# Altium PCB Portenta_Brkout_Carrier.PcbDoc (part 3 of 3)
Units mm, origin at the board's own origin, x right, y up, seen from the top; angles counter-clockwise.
Board outline 163.96 x 72.14 mm, 4 copper layers (Top, GND, PWR, Bottom), stack 1.612 mm thick; 71 components, 171 nets, 700 pads, 387 vias.
Unrouted connection lines stored in the file: 2.
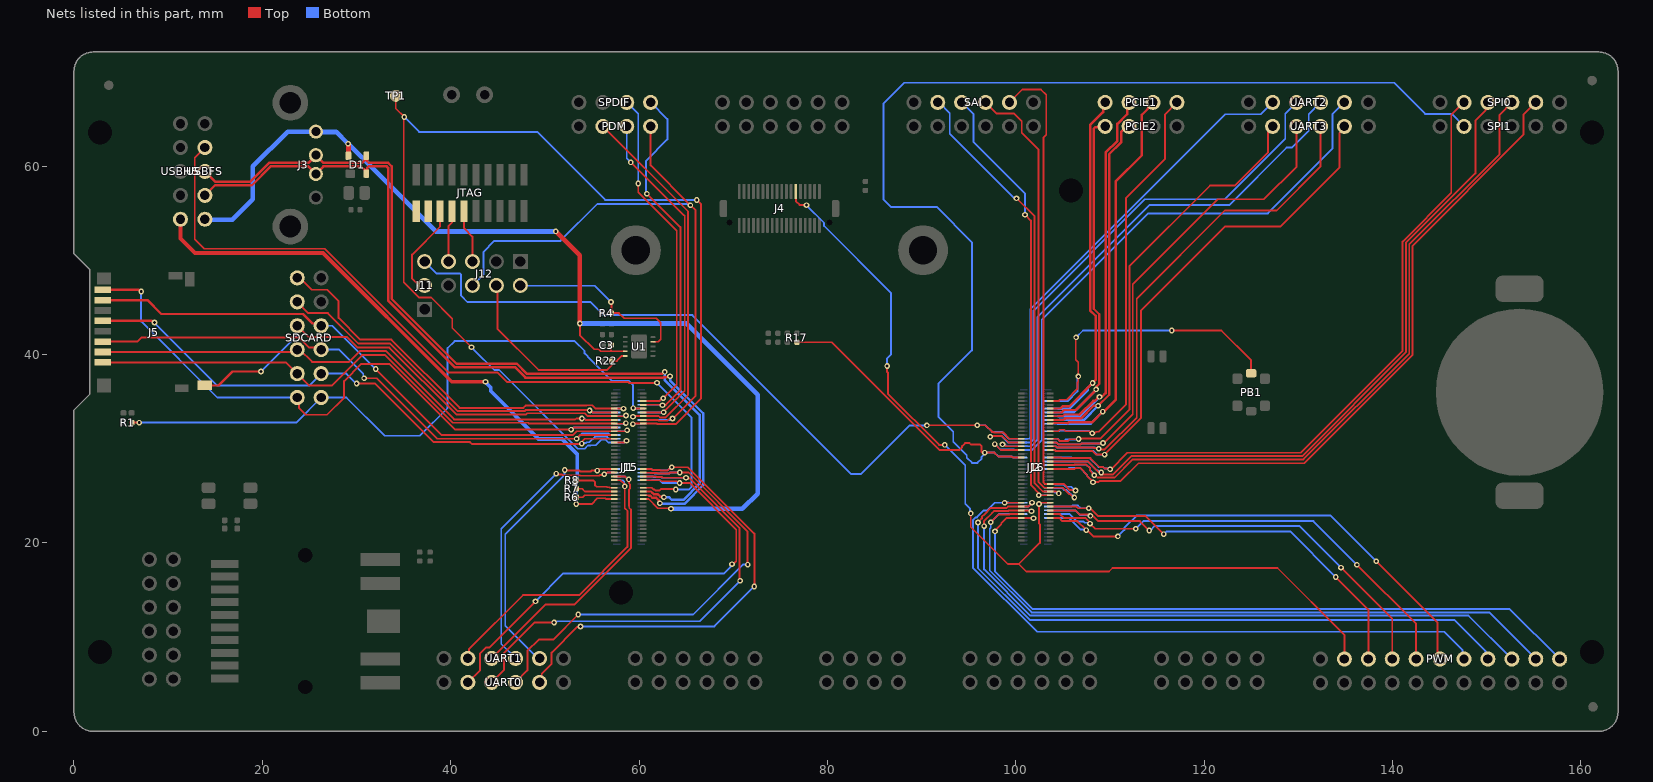
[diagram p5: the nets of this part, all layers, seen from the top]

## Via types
v1: diameter 0.6, hole 0.3, Top to Bottom, tented both sides, 387 vias

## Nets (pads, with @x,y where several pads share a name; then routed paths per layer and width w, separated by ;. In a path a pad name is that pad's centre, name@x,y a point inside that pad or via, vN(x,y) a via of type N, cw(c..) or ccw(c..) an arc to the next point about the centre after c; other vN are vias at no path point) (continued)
PCIE.CK_1_P: J2.17 J16.17 PCIE1.3 | length 47.5
  Top w0.19: J2.17@103.65,32.664 103.959,32.664 104.026,32.731 105.478,32.731 105.52,32.689
  Top w0.264: 105.52,32.689 105.671,32.84 108.132,32.84 v1(109.242,33.949) ; v1@109.353,33.97 109.497,34.114 109.533,34.114 110.6,35.181 110.6,58.362 113.384,61.146 113.384,65.452 114.58,66.648 PCIE1.3@114.58,66.78
  Bottom w0.19: J16.17@103.41,32.664 104.484,32.664
  Bottom w0.264: 104.484,32.664 105.558,32.664 105.572,32.678 107.97,32.678 v1(109.242,33.949)
PCIE.RST_1: J2.21 J16.21 PCIE1.4 | length 48.7
  Top w0.19: J2.21@103.65,31.864 104.52,31.864 104.523,31.866
  Top w0.2: 104.523,31.866 104.674,32.018 105.13,32.018 105.285,31.863 107.802,31.863 108.011,31.654 v1(108.119,31.654) ; v1@108.119,31.501 108.227,31.501 108.537,31.811 108.799,31.811 111.723,34.734 111.723,56.644 115.864,60.784 115.864,65.524 PCIE1.4@117.12,66.78
  Bottom w0.19: J16.21@103.41,31.864 104.622,31.864 104.676,31.919 105.218,31.919 105.249,31.888 107.774,31.888 108.008,31.654 v1(108.119,31.654)
PCIE.RX_1_N: J2.15 J16.15 PCIE2.2 | length 42.9
  Top w0.2: J2.15@103.65,33.064 105.105,33.064 105.182,33.141
  Top w0.264: 105.182,33.141 105.272,33.231 106.934,33.231 108.267,34.564 v1(108.752,34.564) 109.927,35.74 109.927,61.281 111.183,62.536 111.183,63.624 111.799,64.24 PCIE2.2@112.04,64.24
  Bottom w0.2: J16.15@103.41,33.064 103.415,33.069 104.699,33.069
  Bottom w0.264: 104.699,33.069 107.256,33.069 v1(108.752,34.564)
PCIE.RX_1_P: J2.13 J16.13 PCIE1.2 | length 45.2
  Top w0.19: J2.13@103.65,33.464 104.525,33.464
  Top w0.2: 104.525,33.464 104.99,33.464 105.031,33.505 105.038,33.505 105.155,33.622 106.72,33.622
  Top w0.264: 106.72,33.622 106.772,33.622 108.242,35.093 108.389,35.093 108.81,35.514 108.992,35.514 109.056,35.578 109.212,35.578 109.536,35.902 109.536,61.443 110.792,62.698 110.792,64.49 111.824,65.522 111.824,66.564 PCIE1.2@112.04,66.78
  Bottom w0.19: J16.13@103.41,33.464 104.525,33.464
  Bottom w0.264: 104.525,33.464 106.851,33.464 v1(108.901,35.514)
PCIE.TX_1_N: J2.11 J16.11 PCIE2.1 | length 41.5
  Top w0.19: J2.11@103.65,33.864 104.872,33.864
  Top w0.264: 104.872,33.864 104.889,33.864 105.142,34.117 106.401,34.117 108.538,36.254 v1(108.538,36.304) ; v1@108.557,36.273 108.602,36.318 108.602,36.631 108.866,36.895 108.866,44.287 108.289,44.863 108.289,63.994 108.444,64.149 109.409,64.149 PCIE2.1@109.5,64.24
  Bottom w0.19: J16.11@103.41,33.864 104.795,33.864
  Bottom w0.264: 104.795,33.864 106.148,33.864 108.538,36.254 v1(108.538,36.304)
PCIE.TX_1_P: J2.9 J16.9 PCIE1.1 | length 42.5
  Top w0.19: J2.9@103.65,34.264 104.736,34.264 104.756,34.284
  Top w0.264: 104.756,34.284 104.98,34.509 105.689,34.509 v1(108.166,36.986) 108.166,37 108.474,37.309 108.474,44.125 107.898,44.701 107.898,64.361 109.283,65.745 109.283,66.563 PCIE1.1@109.5,66.78
  Bottom w0.19: J16.9@103.41,34.264 104.525,34.264
  Bottom w0.264: 104.525,34.264 105.714,34.264 107.645,36.195 107.645,36.465 v1(108.166,36.986)
PDM.CK_1: J1.66 J12.6 J15.66 PDM.1 | length 68.8
  Top w0.2: J1.66@60.47,33.064 62.001,33.064 62.086,32.979 62.986,32.979 63.14,33.133 63.53,33.133 66.009,35.612 66.009,55.311 v1(65.454,55.866) 61.24,60.08 PDM.1@61.24,64.24
  Bottom w0.2: J12.6@42.314,47.341 43.469,48.495 43.469,50.885 44.651,52.067 51.651,52.067 55.573,55.989 65.137,55.989 65.184,55.943 65.377,55.943 v1(65.454,55.866) ; J15.66@60.23,33.064 63.306,33.064 63.452,33.209 v1(63.56,33.209)
PDM.D0_1: J1.68 J15.68 PDM.3 | length 40.1
  Top w0.2: PDM.3@56.16,64.24 65.202,55.198 65.202,35.689 62.841,33.329 62.231,33.329 62.096,33.464 61.374,33.464 J1.68@60.47,33.464 59.422,33.464 v1(59.364,33.406)
  Bottom w0.2: v1(59.364,33.406) 59.422,33.464 J15.68@60.23,33.464
PDM.D1_1: J1.70 J15.70 PDM.2 | length 38.3
  Top w0.2: v1(59.115,60.411) 64.725,54.801 64.852,54.801 64.852,36.144 62.729,34.021 62.589,34.021 62.588,34.022 62.43,33.864 J1.70@60.47,33.864 ; v1@62.527,33.961 62.529,33.961 v1(62.611,33.879)
  Bottom w0.19: J15.70@60.49,33.864 62.596,33.864 v1(62.611,33.879)
  Bottom w0.2: PDM.2@58.7,64.24 58.7,60.845 59.115,60.43 v1(59.115,60.411)
PWM0_1: J2.59 J4.12 J16.59 PWM.10 | length 100.7
  Top w0.19: v1(95.232,23.138) 95.232,21.695 99.159,17.768 100.331,17.768 ; v1(102.473,24.143) 102.473,22.062 102.564,21.971 102.564,20.001 100.331,17.768 ; v1@102.669,24.264 J2.59@103.65,24.264 ; PWM.10@134.9,7.68 134.9,10.243 127.8,17.343 110.279,17.343 109.905,16.969 101.131,16.969 100.331,17.768
  Top w0.2: J4.12@76.65,57.324 76.65,56.289 77.05,55.889 v1@77.75,55.889 ; v1(86.345,38.781) 86.345,38.159 86.422,38.081 86.422,35.853 91.861,30.414 v1(92.466,30.414)
  Bottom w0.19: v1(92.466,30.414) 94.1,28.78 94.1,28.771 94.638,28.232 94.638,24.166 95.154,23.651 95.154,23.216 v1(95.232,23.138) ; v1@102.708,24.264 J16.59@103.41,24.264
  Bottom w0.2: v1@77.775,55.864 79.643,53.996 79.643,53.661 86.776,46.529 86.776,40.022 86.345,39.591 v1(86.345,38.781)
  other v1: 77.789,55.871
PWM1_1: J2.61 J16.61 PWM.9 | length 48.3
  Top w0.19: J2.61@103.65,23.864 104.285,23.864 104.293,23.857 104.693,23.857 104.7,23.864
  Top w0.2: 104.7,23.864 106.438,23.864 106.617,23.685 107.859,23.685 108.01,23.534 108.049,23.534 108.711,22.872 113.776,22.872 v1(115.714,20.934) ; v1(133.986,16.381) 137.44,12.927 PWM.9@137.44,7.68
  Bottom w0.19: J16.61@103.41,23.864 105.886,23.864 105.999,23.977 106.617,23.977 106.909,23.685 v1(107.751,23.685)
  Bottom w0.2: v1(115.714,20.934) 115.744,20.934 116.031,21.221 129.146,21.221 v1(133.986,16.381)
PWM2_1: J2.63 J16.63 PWM.8 | length 50.5
  Top w0.2: J2.63@103.65,23.464 106.343,23.464 106.793,23.014 107.963,23.014 v1@108,22.977 ; v1(107.928,22.877) v1@107.928,22.942 ; v1@108.074,23.011 108.764,22.321 113.177,22.321 v1(114.181,21.317) ; v1(134.546,17.38) 139.98,11.946 PWM.8@139.98,7.68
  Bottom w0.2: J16.63@103.41,23.464 105.075,23.464 ; 105.075,23.461 106.321,23.461 106.837,22.946 107.86,22.946 v1(107.928,22.877) ; v1(114.181,21.317) 114.289,21.317 114.784,21.812 130.114,21.812 v1(134.546,17.38)
PWM3_1: J2.65 J16.65 PWM.7 | length 53.1
  Top w0.19: J2.65@103.65,23.064 104.7,23.064
  Top w0.2: 104.7,23.064 105.1,22.664 107.364,22.664 107.891,22.137 v1(107.891,22.056) ; v1@107.938,22.117 107.938,22.009 108.439,21.508 v1(112.745,21.508) ; v1(136.229,17.694) 142.52,11.403 PWM.7@142.52,7.68
  Bottom w0.19: J16.65@103.41,23.064 105.729,23.064 106.529,22.264 107.208,22.264 107.337,22.134 107.813,22.134 v1(107.891,22.056)
  Bottom w0.2: v1(112.745,21.508) 113.56,22.323 131.6,22.323 v1(136.229,17.694)
PWM4_1: J2.67 J16.67 PWM.6 | length 56.3
  Top w0.2: J2.67@103.65,22.664 104.605,22.664 104.955,22.314 106.541,22.314 107.421,21.434 v1@107.421,21.366 ; v1(107.489,21.366) 107.597,21.366 108.291,20.672 110.823,20.672 v1(110.845,20.694) ; v1(138.289,18.057) 144.797,11.549 144.797,7.943 PWM.6@145.06,7.68
  Bottom w0.2: J16.67@103.41,22.664 105.641,22.664 106.889,21.416 107.439,21.416 v1(107.489,21.366) ; v1(110.845,20.694) 111.538,21.387 111.538,21.6 112.835,22.897 133.449,22.897 v1(138.289,18.057)
PWM5_1: J2.60 J16.60 PWM.5 | length 69.6
  Top w0.2: v1(98.819,24.273) 98.828,24.264 J2.60@100.57,24.264
  Bottom w0.2: J16.60@100.83,24.264 99.275,24.264 99.223,24.315 98.861,24.315 v1(98.819,24.273) 97.766,24.273 96.958,23.465 96.627,23.465 95.879,22.717 95.766,22.717 95.444,22.395 95.444,17.389 102.268,10.565 145.517,10.565 147.423,8.659 147.423,7.857 PWM.5@147.6,7.68
PWM6_1: J2.62 J16.62 PWM.4 | length 71.1
  Top w0.19: J2.62@100.57,23.864 101.317,23.864 v1(101.736,24.283)
  Top w0.2: v1(95.994,22.167) 95.994,22.184 96.416,22.606 96.416,22.78 96.706,23.07 97.359,23.723 98.591,23.723 99.047,23.723 99.188,23.864 J2.62@100.57,23.864
  Bottom w0.19: J16.62@100.83,23.864 101.317,23.864 v1(101.736,24.283)
  Bottom w0.2: v1(95.994,22.167) 95.994,17.334 101.528,11.8 146.622,11.8 149.872,8.55 149.872,7.948 PWM.4@150.14,7.68
PWM7_1: J2.64 J16.64 PWM.3 | length 71.5
  Top w0.2: v1(96.641,21.787) 96.641,22.335 97.485,23.18 97.678,23.373 98.446,23.373 99.192,23.373 99.283,23.464 J2.64@100.57,23.464 101.473,23.464 101.564,23.373 v1(101.672,23.373)
  Bottom w0.19: J16.64@100.83,23.464 101.47,23.464 101.561,23.373 v1(101.672,23.373)
  Bottom w0.2: v1(96.641,21.787) 96.641,17.182 101.54,12.283 148.077,12.283 PWM.3@152.68,7.68
PWM8_1: J2.66 J16.66 PWM.2 | length 74.5
  Top w0.2: v1(97.346,22.19) 98.17,23.014 99.328,23.014 99.378,23.064 J2.66@100.57,23.064
  Bottom w0.2: J16.66@100.83,23.064 98.22,23.064 v1(97.346,22.19) 97.346,21.59 97.244,21.488 97.244,17.074 101.685,12.633 150.267,12.633 PWM.2@155.22,7.68
PWM9_1: J2.68 J16.68 PWM.1 | length 73.6
  Top w0.2: v1(97.794,21.225) 97.794,21.307 98.466,21.979 98.466,22.068 99.062,22.664 J2.68@100.57,22.664 v1@101.72,22.664
  Bottom w0.19: J16.68@100.83,22.664 v1@101.72,22.664
  Bottom w0.2: v1(97.794,21.225) 97.794,17.019 101.83,12.983 152.457,12.983 PWM.1@157.76,7.68
  other v1: 101.88,22.629
PWRON_1: J2.5 J16.5 PB1.6 | length 35.9
  Top w0.19: J2.5@103.65,35.064 104.554,35.064 104.693,35.203 105.401,35.203 106.552,36.354 106.552,37.008 106.647,37.103 106.647,37.684 v1(106.65,37.688) ; v1(106.409,41.824) 106.376,41.791 106.376,39.458 106.65,39.184 106.65,37.823 106.552,37.725 v1@106.572,37.705
  Top w0.2: v1(116.561,42.559) 121.83,42.559 125,39.389 PB1.6@125,38.015
  Bottom w0.19: J16.5@103.41,35.064 105.533,35.064 106.552,36.083 106.552,37.478 106.65,37.577 v1(106.65,37.688)
  Bottom w0.2: v1(106.409,41.824) 107.144,42.559 v1(116.561,42.559)
SAI.CK_1: J2.49 J16.49 SAI.2 | length 53
  Top w0.2: SAI.2@99.34,66.78 100.709,68.149 102.682,68.149 103.241,67.59 103.241,63.332 102.932,63.023 102.932,26.436 103.104,26.264 J2.49@103.65,26.264 105.101,26.264 105.747,25.618 106.3,25.618 v1(106.347,25.571)
  Bottom w0.2: J16.49@103.41,26.264 104.114,26.264 104.164,26.214 104.245,26.214 104.26,26.199 105.09,26.199 105.322,25.967 105.895,25.967 106.291,25.571 v1(106.347,25.571)
SAI.D0_1: J2.53 J16.53 SAI.5 | length 49.2
  Top w0.19: v1(100.085,56.587) 102,54.672 102,26.333 102.869,25.464 J2.53@103.65,25.464 104.264,25.464 104.461,25.268 v1(104.565,25.268)
  Bottom w0.19: SAI.5@91.72,66.78 91.861,66.78 93.003,65.638 93.003,63.456 96.398,60.061 99.794,56.665 100.007,56.665 v1(100.085,56.587) ; J16.53@103.41,25.464 103.905,25.464 104.055,25.464 104.173,25.346 104.487,25.346 v1(104.565,25.268)
SAI.D1_1: J2.55 J16.55 SAI.4 | length 47.1
  Top w0.2: v1(100.991,54.856) 101.611,54.236 101.611,26.156 102.573,25.194 102.703,25.064 J2.55@103.65,25.064
  Bottom w0.2: SAI.4@94.26,66.78 95.519,65.521 95.519,62.544 100.991,57.072 v1(100.991,54.856) ; v1(102.443,25.064) J16.55@103.41,25.064
SAI.FS_1: J2.51 J16.51 SAI.3 | length 51.5
  Top w0.2: SAI.3@96.8,66.78 97.988,65.592 99.842,65.592 100.645,64.79 100.645,63.537 102.4,61.781 102.4,26.498 102.449,26.449 102.449,26.424 103.009,25.864 105.006,25.864 105.692,25.178 105.771,25.178 106.118,24.831 v1(106.226,24.831)
  Bottom w0.2: J16.51@103.41,25.864 104.1,25.864 104.115,25.849 104.945,25.849 105.177,25.617 105.413,25.617 106.199,24.831 v1(106.226,24.831)
SDC.CD_1: J1.67 J5.CD1 J15.67 SDCARD.8 | length 52.9
  Top w0.19: J1.67@57.39,33.464 58.559,33.464 v1(58.624,33.529)
  Top w0.2: J5.CD1@14.075,36.73 15.352,36.73 ; SDCARD.8@23.71,43.064 24.912,41.862 29.018,41.862 30.141,40.739 33.499,40.739 40.593,33.645 48.012,33.645 48.136,33.769 54.238,33.769 54.544,33.464 J1.67@57.39,33.464
  Top w0.254: 15.352,36.73 16.829,38.207 v1(19.864,38.207)
  Bottom w0.19: J15.67@57.65,33.464 58.559,33.464 v1(58.624,33.529)
  Bottom w0.2: v1@19.849,38.2 19.857,38.2 23.663,42.006 23.663,43.017 SDCARD.8@23.71,43.064
SDC.CLK_1: J1.55 J5.5 J15.55 SDCARD.3 | length 65.1
  Top w0.2: v1@29.998,36.919 31.995,36.919 38.2,30.714 42.051,30.714 42.251,30.514 53.735,30.514 53.869,30.647 v1@53.869,30.687 ; v1(53.92,30.549) 53.92,30.636 v1@53.869,30.687 ; J1.55@57.39,31.064 54.246,31.064 v1@53.869,30.687
  Top w0.254: J5.5@3.075,43.58 8.278,43.58 8.462,43.396 v1@8.535,43.396
  Bottom w0.19: v1(53.92,30.549) 53.999,30.627 54.361,30.627 54.421,30.687 54.73,30.687 55.337,31.294 56.588,31.294 56.818,31.064 J15.55@57.39,31.064
  Bottom w0.2: v1@8.535,43.396 15.217,36.714 24.98,36.714 SDCARD.3@26.25,37.984 28.933,37.984 v1@29.998,36.919
  other v1: 30.012,36.925 8.549,43.402
SDC.CMD_1: J1.57 J5.3 J15.57 SDCARD.5 | length 63.7
  Top w0.2: J5.3@3.262,41.38 6.746,41.38 7.167,41.801 23.918,41.801 24.986,40.733 26.041,40.733 SDCARD.5@26.25,40.524 ; v1@30.8,37.489 32.175,37.489 38.6,31.064 v1(53.375,31.064) 53.775,31.464 J1.57@57.39,31.464
  Bottom w0.2: SDCARD.5@26.25,40.524 28.171,40.524 30.715,37.98 30.715,37.574 v1@30.8,37.489 ; v1(53.375,31.064) 53.95,31.639 56.731,31.639 56.906,31.464 J15.57@57.65,31.464
  other v1: 30.814,37.496
SDC.D0_1: J1.59 J5.7 J15.59 SDCARD.7 | length 62.7
  Top w0.19: J1.59@57.39,31.864 58.525,31.864 58.625,31.964 v1(58.736,31.964)
  Top w0.2: v1@32.051,38.46 39.066,31.445 52.978,31.445 53.397,31.864 J1.59@57.39,31.864
  Top w0.254: J5.7@3.262,45.78 7.802,45.78 9.271,44.311 24.306,44.311 25.32,43.297 26.018,43.297 SDCARD.7@26.25,43.064
  Bottom w0.19: J15.59@57.65,31.864 58.525,31.864 58.625,31.964 v1(58.736,31.964)
  Bottom w0.2: SDCARD.7@26.25,43.064 27.426,43.064 v1@32.03,38.46
  other v1: 32.044,38.466
SDC.D1_1: J1.61 J5.8 J15.61 SDCARD.2 | length 73.6
  Top w0.19: J1.61@57.39,32.264 J1.61@57.65,32.264
  Top w0.2: SDCARD.2@23.71,35.444 23.889,35.265 23.889,34.344 24.617,33.616 26.87,33.616 28.691,35.437 28.691,37.176 30.531,39.016 33.483,39.016 40.466,32.033 v1(52.788,32.033) ; v1@52.798,32.11 52.973,32.11 53.128,32.264 J1.61@57.39,32.264
  Top w0.254: J5.8@3.075,46.88 6.883,46.88 7.065,46.698 v1@7.138,46.698
  Bottom w0.19: v1(52.788,32.033) 52.828,32.033 53.059,32.264 57.319,32.264 J15.61@57.65,32.264
  Bottom w0.2: v1@7.138,46.698 7.138,43.523 15.217,35.444 SDCARD.2@23.71,35.444
  other v1: 7.152,46.704
SDC.D2_1: J1.63 J5.1 J15.63 SDCARD.4 | length 61.7
  Top w0.19: J1.63@57.39,32.664 58.545,32.664 v1(58.607,32.726)
  Top w0.2: J5.1@3.262,39.18 22.514,39.18 24.983,36.711 27.377,36.711 30.605,39.939 33.055,39.939 40.23,32.764 48.215,32.764 48.315,32.664 J1.63@57.39,32.664
  Bottom w0.19: J15.63@57.65,32.664 58.545,32.664 v1(58.607,32.726)
SDC.D3_1: J1.65 J5.2 J15.65 SDCARD.6 | length 62.5
  Top w0.19: J1.65@57.39,33.064 J1.65@57.65,33.064
  Top w0.2: J5.2@3.262,40.28 23.466,40.28 SDCARD.6@23.71,40.524 ; SDCARD.6@23.715,40.259 23.98,40.524 25.283,39.221 29.238,39.221 30.406,40.389 33.1,40.389 40.375,33.114 53.23,33.114 53.33,33.214 v1(53.93,33.214) ; v1(53.93,33.214) v1@54.089,33.212 ; v1@54.096,33.159 54.209,33.159 54.304,33.064 J1.65@57.39,33.064
  Bottom w0.19: v1(53.93,33.214) 53.935,33.219 54.207,33.219 54.362,33.064 J15.65@57.65,33.064
SDC.RST_1: J1.71 J15.71 SDCARD.12 | length 42.4
  Top w0.2: SDCARD.12@23.71,48.144 23.98,48.144 25.235,46.889 26.886,46.889 28.093,45.682 28.093,43.896 30.4,41.589 33.71,41.589 40.954,34.345 47.722,34.345 47.952,34.576 54.384,34.576 54.425,34.617 55.032,34.617 55.235,34.414 55.244,34.414 55.394,34.264 J1.71@57.39,34.264 v1(58.352,34.264)
  Bottom w0.2: J15.71@57.65,34.264 v1(58.352,34.264)
SDC.WP_1: J1.69 J15.69 SDCARD.10 | length 41.9
  Top w0.19: J1.69@57.39,33.864 J1.69@57.65,33.864
  Top w0.2: SDCARD.10@23.71,45.604 24.902,44.412 26.963,44.412 30.215,41.16 33.573,41.16 40.738,33.995 47.867,33.995 47.991,34.119 54.705,34.119 v1(54.76,34.064) 54.868,34.064 55.068,33.864 J1.69@57.39,33.864
  Bottom w0.19: v1(54.76,34.064) 54.871,34.064 55.071,33.864 55.136,33.864 ; 55.136,33.864 J15.69@57.65,33.864
SPDIF.RX_1: J1.76 J15.76 SPDIF.2 | length 38.7
  Top w0.19: J1.76@60.47,35.064 60.71,35.064 61.49,35.064 62.075,35.064
  Top w0.2: v1(59.923,58.168) 59.923,57.221 64.011,53.133 64.011,36.798 v1@62.576,35.363 ; 62.075,35.064 62.168,35.064 62.47,35.365 v1(62.576,35.365)
  Bottom w0.19: J15.76@60.47,35.064 62.166,35.064 62.467,35.365 v1(62.576,35.365)
  Bottom w0.2: SPDIF.2@58.7,66.78 59.923,65.557 v1(59.923,58.168)
SPDIF.TX_1: J1.74 J15.74 SPDIF.1 | length 40.6
  Top w0.19: J1.74@60.47,34.664 61.25,34.664 62.448,34.664 v1(62.493,34.62) ; v1@62.493,34.664 62.862,34.664
  Top w0.2: v1(60.837,57.085) 64.391,53.531 64.391,36.193 62.862,34.664
  Bottom w0.19: J15.74@60.23,34.664 62.448,34.664 v1(62.493,34.62)
  Bottom w0.2: v1(60.837,57.085) 60.761,57.161 60.761,60.586 63.018,62.843 63.018,65.002 SPDIF.1@61.24,66.78
SPI0.CIPO_1: J2.39 J16.39 SPI0.4 | length 81.4
  Top w0.2: J2.39@103.65,28.264 105.783,28.264 105.789,28.27 106.197,28.27 106.241,28.314 107.493,28.314 107.893,27.914 107.893,27.662 108.243,27.312 v1@108.495,27.312 ; v1(108.338,27.185) 108.368,27.185 v1@108.495,27.312 ; SPI0.4@152.68,66.78 151.37,65.47 151.37,61.293 141.783,51.706 141.783,40.113 130.549,28.879 112.438,28.879 110.489,26.93 108.702,26.93 108.523,27.109 108.507,27.109 108.495,27.097 v1@108.495,27.312
  Bottom w0.2: J16.39@103.41,28.264 105.464,28.264 105.507,28.308 107.499,28.308 107.896,27.911 107.896,27.733 108.338,27.29 v1(108.338,27.185)
SPI0.CK_1: J2.37 J16.37 SPI0.3 | length 80.2
  Top w0.2: J2.37@103.65,28.664 107.638,28.664 109.022,27.28 110.34,27.28 112.289,29.229 130.404,29.229 141.433,40.258 141.433,51.851 148.816,59.234 148.816,64.851 149.896,65.931 149.896,66.536 SPI0.3@150.14,66.78 ; v1@109.088,27.299 v1(109.088,27.48)
  Bottom w0.2: J16.37@103.41,28.664 107.638,28.664 108.578,27.724 108.736,27.724 108.98,27.48 v1(109.088,27.48)
SPI0.COPI_1: J2.41 J16.41 SPI0.5 | length 82.6
  Top w0.19: J2.41@103.65,27.864 106.271,27.864 106.349,27.942 106.357,27.942 106.379,27.964 106.817,27.964
  Top w0.2: 106.817,27.964 106.827,27.964 107.592,27.199 107.592,27.106 108.209,26.489 v1(108.209,26.446) ; v1@108.231,26.467 108.243,26.48 108.809,26.48 108.909,26.58 111.152,26.58 113.036,28.464 130.629,28.464 142.133,39.968 142.133,51.561 153.91,63.338 153.91,65.47 SPI0.5@155.22,66.78
  Bottom w0.19: J16.41@103.41,27.864 105.551,27.864 105.65,27.963 106.821,27.963 107.592,27.192 107.592,27.106 108.209,26.489 v1(108.209,26.446)
SPI0.CS_1: J2.35 J16.35 SPI0.2 | length 79.4
  Top w0.2: J2.35@103.65,29.064 104.883,29.064 104.933,29.014 107.925,29.014 108.875,28.064 109.282,28.064 109.44,27.907 109.948,27.907 v1(110.025,27.83) ; v1@110.069,27.786 111.861,29.579 130.259,29.579 141.083,40.403 141.083,51.996 146.25,57.163 146.25,65.466 147.564,66.78 SPI0.2@147.6,66.78
  Bottom w0.19: J16.35@103.41,29.064 105.942,29.064 105.997,29.009 107.846,29.009 108.786,28.069 109.27,28.069 109.44,27.899 109.956,27.899 v1(110.025,27.83)
SPI1.CS_1: J2.36 J16.36 R17.2 SPI1.2 | length 148.4
  Top w0.2: R17.2@76.773,41.314 80.466,41.314 91.916,29.864 93.99,29.864 94.298,30.172 94.298,30.287 94.62,30.609 95.076,30.609 95.226,30.459 96.199,30.459 96.386,30.272 96.386,29.651 96.573,29.464 v1(96.705,29.596) 97.732,29.596 98.149,29.179 99.583,29.179 99.638,29.124 99.664,29.124 99.724,29.064 J2.36@100.57,29.064
  Bottom w0.2: v1(96.705,29.596) 96.705,29.488 96.375,29.157 96.375,28.936 95.93,28.492 95.361,28.492 94.795,29.058 94.795,29.334 93.366,30.763 93.366,31.805 91.793,33.378 91.793,36.89 95.348,40.445 95.348,51.923 91.596,55.675 86.747,55.675 85.95,56.472 85.95,66.629 88.185,68.864 140.172,68.864 143.478,65.558 146.282,65.558 SPI1.2@147.6,64.24 ; v1@96.721,29.596 97.727,29.596 98.139,29.184 98.358,29.184 98.378,29.164 99.622,29.164 99.723,29.064 J16.36@100.53,29.064
TRACEDATA0_1: J12.7 JTAG.14 | length 5.5
  Top w0.127: JTAG.14@40.154,55.236 40.154,54.086 40.164,54.076
  Top w0.2: J12.7@39.774,49.881 39.774,53.686 40.164,54.076
TRACEDATA1_1: J11.2 JTAG.16 | length 10
  Top w0.2: J11.2@37.234,47.341 36.967,47.608 36.421,47.608 36.413,47.616 36.354,47.616 35.898,48.072 35.898,50.615 38.884,53.601 JTAG.16@38.884,55.236
TRACEDATA2_1: JTAG.18
TRACEDATA3_1: JTAG.20
TRACEDATACLK_1: J12.5 JTAG.12 | length 5.7
  Top w0.2: JTAG.12@41.424,55.236 41.424,53.421 42.314,52.531 J12.5@42.314,49.881
U\S\B\A\_\V\B\U\S\_\E\N\_1: J12.2 R4.1 U1.4 | length 20
  Top w0.2: v1(57.029,45.581) 57.069,45.541 R4.1@57.069,44.413 57.868,44.413 58.425,43.856 61.833,43.856 62.302,43.388 62.302,43.238 62.309,43.23 62.309,41.625 62.042,41.358 U1.4@61.484,41.358
  Bottom w0.2: J12.2@47.283,47.311 55.299,47.311 v1(57.029,45.581)
U\S\B\A\_\V\B\U\S\_\F\L\A\G\_1: J12.4 R22.2 U1.10 | length 20.9
  Top w0.2: J12.4@44.962,47.319 44.962,42.738 49.328,38.372 56.618,38.372 57.069,38.823 R22.2@57.069,39.329 57.65,39.329 58.18,39.858 U1.10@58.534,39.858
UART0.CTS_1: J1.40 J15.40 UART0.5 | length 52.1
  Top w0.19: J1.40@60.47,27.864 60.471,27.863 61.323,27.863 61.431,27.755 61.996,27.755 61.997,27.754
  Top w0.2: UART0.5@49.44,5.2 49.671,5.431 49.671,6.125 50.711,7.165 50.711,8.357 53.412,11.058 53.708,11.058 v1(53.785,11.134) ; 61.997,27.754 62.229,27.754 62.274,27.709 63.045,27.709 63.368,28.032 v1(63.476,28.032) ; v1@63.494,28.049 63.511,28.032 65.199,28.032 72.244,20.987 v1(72.244,15.377)
  Bottom w0.19: J15.40@60.23,27.864 61.316,27.864 61.424,27.756 61.824,27.756 61.866,27.714 63.047,27.714 63.365,28.032 v1(63.476,28.032)
  Bottom w0.2: v1(53.785,11.134) 68.001,11.134 v1(72.244,15.377)
UART0.RTS_1: J1.38 J15.38 UART0.4 | length 52.5
  Top w0.19: J1.38@60.47,27.464 60.471,27.463 61.214,27.463 61.262,27.415 61.926,27.415 61.977,27.365
  Top w0.2: UART0.4@46.9,5.2 48.158,6.458 48.158,8.535 49.362,9.739 50.877,9.739 v1(53.54,12.402) ; 61.977,27.365 61.982,27.359 63.19,27.359 63.313,27.482 65.254,27.482 71.538,21.198 v1(71.538,17.702)
  Bottom w0.19: J15.38@60.23,27.464 61.166,27.464 61.219,27.411 61.522,27.411
  Bottom w0.2: v1(53.54,12.402) 65.734,12.402 71.034,17.702 v1(71.538,17.702) ; 61.522,27.411 61.624,27.411 61.666,27.369 63.19,27.369 63.303,27.482 v1(64.319,27.482)
UART0.RX_1: J1.36 J15.36 UART0.3 | length 54.8
  Top w0.19: J1.36@60.47,27.064 61.657,27.064
  Top w0.2: UART0.3@44.36,5.2 45.651,6.491 45.651,8.287 48.921,11.557 v1(50.99,11.557) ; 61.657,27.064 61.782,27.064 61.837,27.009 62.418,27.009 62.505,26.922 v1(64.991,26.922) ; v1@65.013,26.899 65.067,26.845 65.396,26.845 70.68,21.561 70.68,16.043 v1(70.736,15.987)
  Bottom w0.19: J15.36@60.23,27.064 61.134,27.064
  Bottom w0.2: v1(50.99,11.557) 51.067,11.634 51.257,11.634 51.308,11.684 66.433,11.684 v1(70.736,15.987) ; 61.134,27.064 61.477,27.064 61.522,27.019 62.326,27.019 62.423,26.922 v1(64.991,26.922)
UART0.TX_1: J1.34 J15.34 UART0.2 | length 54.6
  Top w0.19: J1.34@60.47,26.664 62.276,26.664 62.384,26.555
  Top w0.2: UART0.2@41.82,5.2 43.12,6.5 43.12,8.275 43.756,8.911 44.126,8.911 v1(49.012,13.797) ; 62.384,26.555 63.201,26.555 64.018,26.555 64.201,26.372 65.374,26.372 70.33,21.416 70.33,18.055 70.18,17.905 70.137,17.905 69.988,17.756 v1(69.88,17.756)
  Bottom w0.19: J15.34@60.23,26.664 61.374,26.664
  Bottom w0.2: v1(49.012,13.797) 51.979,16.764 69.039,16.764 69.731,17.457 69.731,17.499 69.88,17.648 v1(69.88,17.756) ; 61.374,26.664 61.379,26.669 62.181,26.669 62.478,26.372 v1(64.309,26.372)
UART1.CTS_1: J1.39 J15.39 UART1.5 | length 31.6
  Top w0.2: v1(52.115,27.753) 52.159,27.709 53.649,27.709 53.778,27.581 54.87,27.581 54.97,27.681 55.567,27.681 v1(55.57,27.684) ; v1@55.579,27.675 55.768,27.864 56.506,27.864 J1.39@57.39,27.864
  Bottom w0.2: UART1.5@49.44,7.74 49.261,7.74 45.797,11.204 45.797,20.949 52.105,27.257 52.105,27.743 v1(52.115,27.753) ; v1(55.57,27.684) 55.65,27.684 55.83,27.864 J15.39@57.35,27.864
UART1.RTS_1: J1.37 J15.37 UART1.4 | length 29.8
  Top w0.2: v1(51.221,27.364) 51.297,27.288 51.803,27.288 51.9,27.19 53.716,27.19 53.772,27.134 55.797,27.134 55.889,27.226 56.24,27.226 v1(56.317,27.303) ; v1@56.317,27.418 56.591,27.418 56.638,27.464 J1.37@57.39,27.464
  Bottom w0.2: UART1.4@46.9,7.74 45.37,9.27 45.37,21.514 v1(51.221,27.364) ; v1@56.564,27.418 56.591,27.418 56.638,27.464 J15.37@57.35,27.464
UART1.RX_1: J1.35 J15.35 UART1.3 | length 30.3
  Top w0.19: J1.35@57.39,27.064 58.488,27.064 58.765,26.787 58.765,26.686 58.866,26.686 58.936,26.616 58.936,26.332 59.035,26.232 59.035,25.781 58.936,25.681 58.936,23.889 58.965,23.86 58.965,23.707 59.162,23.51 59.162,19.481 ; v1@58.802,26.649 v1(58.908,26.754)
  Top w0.2: UART1.3@44.36,7.74 44.36,7.774 50.048,13.462 53.143,13.462 59.162,19.481
  Bottom w0.19: J15.35@57.65,27.064 58.488,27.064 58.797,26.754 v1(58.908,26.754)
UART1.TX_1: J1.33 J15.33 UART1.2 | length 31.8
  Top w0.19: UART1.2@41.82,7.74 41.937,7.857 41.937,8.714 47.693,14.47 ; J1.33@57.39,26.664 58.025,26.664 58.412,26.277 58.412,26.085 v1(58.49,26.007) 58.49,23.701 58.775,23.416 58.775,19.589
  Top w0.2: 47.693,14.47 53.656,14.47 58.775,19.589
  Bottom w0.19: J15.33@57.65,26.664 58.272,26.664 58.417,26.519 58.417,26.08 v1(58.49,26.007)
UART2.CTS_1: J2.32 J16.32 UART2.5 | length 65.4
  Top w0.19: v1(97.771,30.49) 97.807,30.49 98.433,29.864 J2.32@100.57,29.864
  Bottom w0.19: v1(97.771,30.49) 97.802,30.49 98.368,29.924 99.831,29.924 99.891,29.864 J16.32@100.83,29.864 101.713,29.864 102.765,30.916 102.765,43.694 114.07,54.999
  Bottom w0.2: 114.07,54.999 126.769,54.999 133.622,61.852 133.622,65.502 UART2.5@134.9,66.78
UART2.RTS_1: J2.30 J16.30 UART2.4 | length 59.7
  Top w0.19: v1(98.599,30.469) 98.677,30.39 98.814,30.39 98.94,30.264 J2.30@100.57,30.264
  Bottom w0.19: v1(98.599,30.469) 98.677,30.39 98.916,30.39 99.042,30.264 J16.30@100.83,30.264
  Bottom w0.2: J16.30@100.83,30.264 101.625,30.264 102.295,30.934 102.295,43.969 114.198,55.872 122.653,55.872 128.752,61.971 129.3,61.971 131.12,63.791 131.12,65.54 UART2.4@132.36,66.78
UART2.RX_1: J2.28 J16.28 UART2.3 | length 60.9
  Top w0.19: v1(97.296,31.271) 97.373,31.348 98.563,31.348 99.247,30.664 J2.28@100.57,30.664
  Bottom w0.19: v1(97.296,31.271) 97.373,31.348 97.809,31.348 97.826,31.331 98.507,31.331 99.175,30.664 J16.28@100.83,30.664
  Bottom w0.2: J16.28@100.83,30.664 101.53,30.664 101.895,31.029 101.895,44.674 113.716,56.495 122.186,56.495 128.623,62.933 128.623,65.584 UART2.3@129.82,66.78
UART2.TX_1: J2.26 J11.3 J16.26 UART2.2 | length 131.5
  Top w0.2: v1(90.57,32.483) 90.58,32.493 95.904,32.493 v1(95.913,32.502) 96.77,32.502 97.485,31.787 97.674,31.787 97.713,31.748 98.651,31.748 99.335,31.064 J2.26@100.57,31.064
  Bottom w0.2: J11.3@37.234,49.881 38.493,48.622 40.99,48.622 41.107,48.505 41.107,46.263 41.789,45.581 54.869,45.581 56.261,44.189 65.666,44.189 82.55,27.305 83.566,27.305 88.744,32.483 v1(90.57,32.483) ; v1(95.913,32.502) 96.77,32.502 97.485,31.787 98.539,31.787 99.262,31.064 J16.26@100.83,31.064 101.428,31.064 101.545,31.181 101.545,44.819 122.241,65.515 126.015,65.515 UART2.2@127.28,66.78
UART3.CTS_1: J2.31 J16.31 UART3.5 | length 61.3
  Top w0.2: J2.31@103.65,29.864 104.149,29.864 104.239,29.774 108.141,29.774 108.506,29.409 v1@109.338,29.409 ; v1@109.338,29.475 v1(109.436,29.377) ; UART3.5@134.9,64.24 134.9,64.067 134.392,63.559 134.392,59.881 128.102,53.591 122.196,53.591 113.306,44.701 113.306,33.279 v1@109.436,29.409 ; v1@109.338,29.409 v1@109.436,29.409 ; v1@109.338,29.409 v1@109.436,29.409
  Bottom w0.19: J16.31@103.41,29.864 104.17,29.864 104.245,29.789 104.702,29.789 104.707,29.784
  Bottom w0.2: 104.702,29.784 104.707,29.784 108.254,29.784 108.679,29.359 109.418,29.359 v1(109.436,29.377)
UART3.RTS_1: J2.29 J16.29 UART3.4 | length 58.4
  Top w0.2: J2.29@103.65,30.264 104.244,30.264 104.384,30.124 108.286,30.124 108.344,30.066 108.75,30.066 v1(108.814,30.001) ; v1@108.814,29.927 109.459,29.927 112.85,33.318 112.85,45.935 122.215,55.3 127.711,55.3 132.36,59.949 UART3.4@132.36,64.24
  Bottom w0.2: J16.29@103.41,30.264 104.258,30.264 104.388,30.134 108.399,30.134 108.455,30.078 108.738,30.078 v1(108.814,30.001)
UART3.RX_1: J2.27 J16.27 UART3.3 | length 56.8
  Top w0.2: J2.27@103.65,30.664 104.284,30.664 104.334,30.614 104.389,30.614 104.529,30.474 106.893,30.474 106.971,30.551 109.21,30.551 v1(109.267,30.608) ; v1@109.314,30.561 109.609,30.855 112.423,33.669 112.423,47.447 121.476,56.5 126.36,56.5 129.82,59.96 UART3.3@129.82,64.24
  Bottom w0.2: J16.27@103.41,30.664 104.353,30.664 104.533,30.484 106.903,30.484 106.971,30.551 109.21,30.551 v1(109.267,30.608)
UART3.TX_1: J2.25 J16.25 UART3.2 | length 51.3
  Top w0.19: J2.25@103.65,31.064 104.379,31.064 104.436,31.007
  Top w0.2: 104.436,31.007 104.491,31.007 104.674,30.824 105.537,30.824 105.72,31.008 106.649,31.008 v1(106.675,31.034) ; v1@106.691,31.008 106.787,31.104 109.029,31.104 111.684,33.759 112.073,34.148 112.073,49.383 120.629,57.939 123.259,57.939 126.772,61.453 126.772,63.594 127.28,64.102 UART3.2@127.28,64.24
  Bottom w0.19: J16.25@103.41,31.064 104.441,31.064 104.676,30.829 105.128,30.829 105.281,30.982 106.624,30.982 v1(106.675,31.034)
USB_FS.D_1_N: D1.3 J1.28 J3.2 USBFS.3 | length 89.9
  Top w0.2: J1.28@60.47,25.464 61.291,25.464 61.411,25.344
  Top w0.264: USBFS.3@13.91,59.45 14.984,58.376 18.733,58.376 20.723,60.366 24.884,60.366 J3.2@25.689,61.17 26.493,60.366 28.102,60.366 30.566,60.366 30.884,60.684 30.884,60.963 D1.3@31.046,61.125 31.146,61.025 31.146,60.52 31.301,60.366 33.365,60.366 33.748,59.982 33.748,45.905 40.622,39.031 47.027,39.031 48.105,37.953 62.42,37.953 62.634,38.167 v1(62.725,38.167) ; 61.411,25.344 61.565,25.19 61.983,25.19 62.263,24.91 62.579,24.91 v1(62.643,24.846)
  Bottom w0.264: v1(62.643,24.846) 63.202,24.846 63.266,24.782 63.471,24.576 64.707,24.576 66.427,26.296 66.427,33.59 62.725,37.292 v1(62.725,38.167)
USB_FS.D_1_P: D1.2 J1.26 J3.3 USBFS.2 | length 90.3
  Top w0.2: J1.26@60.47,25.064 61.056,25.064 61.102,25.018
  Top w0.264: USBFS.2@13.91,56.91 14.984,57.984 18.895,57.984 20.885,59.974 24.884,59.974 J3.3@25.689,59.17 26.493,59.974 28.264,59.974 30.508,59.974 D1.2@30.993,59.49 ; D1.2@31.046,59.215 31.146,59.315 31.146,59.82 31.301,59.974 33.203,59.974 33.357,59.82 33.357,45.743 40.46,38.64 46.865,38.64 47.943,37.562 62.582,37.562 62.605,37.585 62.934,37.585 62.987,37.638 63.22,37.638 v1(63.284,37.702) ; 61.102,25.018 61.184,25.018 61.403,24.798 61.821,24.798 62.078,24.542 62.078,24.452 62.216,24.314 v1(62.216,24.224)
  Bottom w0.264: v1(62.216,24.224) 62.254,24.185 64.869,24.185 66.818,26.134 66.818,33.752 63.304,37.266 63.304,37.682 v1(63.284,37.702)
USB_FS.ID_1: J1.30 USBFS.4 | length 83.6
  Top w0.2: USBFS.4@13.91,61.99 12.825,60.905 12.825,52.239 13.825,51.239 26.627,51.239 39.785,38.081 44.998,38.081 45.995,37.084 52.415,37.084 52.429,37.099 58.849,37.099 58.945,37.003 v1(61.904,37.003) ; J1.30@60.47,25.864 61.369,25.864 61.564,25.669 61.626,25.669 61.726,25.569 62.181,25.569 62.333,25.721 63.853,25.721 v1(63.905,25.669)
  Bottom w0.2: v1(61.904,37.003) 65.562,33.345 65.562,25.939 65.292,25.669 v1(63.905,25.669)
USB_FS.VBUS_1: C3.1 D1.4 J1.24 J3.1 U1.9 USBFS.1 | length 112.7
  Top w0.19: J1.24@60.47,24.664 61.037,24.664 62.009,23.692 63.33,23.692 v1(63.396,23.626)
  Top w0.2: v1(53.721,43.307) 53.721,42.077 55.234,40.564 55.727,40.564 55.933,40.358 57.04,40.358 U1.9@58.534,40.358 ; 57.029,40.369 C3.1@57.029,41.002
  Top w0.5: D1.4@29.146,61.125 v1@29.146,62.316 ; v1(51.164,53.081) 53.721,50.524 v1(53.721,43.307)
  Bottom w0.5: USBFS.1@13.91,54.37 13.955,54.325 16.825,54.325 19,56.5 19,59.975 22.695,63.67 J3.1@25.689,63.67 25.713,63.646 27.844,63.646 v1@29.1,62.389 ; v1(29.114,62.396) 38.429,53.081 v1(51.164,53.081) ; v1(53.721,43.307) 65.024,43.307 72.597,35.734 72.597,25.247 70.976,23.626 v1(63.396,23.626)
USB_HS.D_1_N: J1.27 R7.2 | length 4.2
  Top w0.2: R7.2@53.35,25.75 53.972,25.75 54.258,25.464 J1.27@57.39,25.464
USB_HS.D_1_P: J1.25 R6.2 | length 4.1
  Top w0.2: R6.2@53.35,24.85 54.033,24.85 54.252,25.069 56.568,25.069 56.574,25.064 J1.25@57.39,25.064
USB_HS.ID_1: J1.29 R8.2 | length 4.5
  Top w0.2: R8.2@53.375,26.65 55.159,26.65 55.312,26.497 55.312,26.151 55.495,25.968 56.565,25.968 56.619,25.914 56.859,25.914 56.909,25.864 J1.29@57.39,25.864
USB_HS.VBUS_1: J1.23 USBHS.1 | length 63.6
  Top w0.2: v1(53.33,24.133) 54.979,24.133 55.588,24.742 56.433,24.742 56.511,24.664 57.082,24.664 J1.23@57.39,24.664
  Top w0.4: USBHS.1@11.31,54.37 11.31,52.34 12.861,50.789 26.441,50.789 40.115,37.115 v1(43.697,37.115)
  Bottom w0.4: v1(43.697,37.115) 43.697,37.061 44.256,36.501 44.256,36.119 49.33,31.045 51.838,31.045 53.43,29.453 53.43,26.94 53.33,26.84 v1(53.33,24.133)
VSD: J1.72 J15.72 R1.1 SDCARD.1 | length 70.3
  Top w0.19: v1@59.5,34.239 59.525,34.264 J1.72@60.47,34.264
  Top w0.2: R1.1@6.175,32.775 v1(6.925,32.775)
  Top w0.5: R1.1@6.175,32.775 R1.1@6.2,32.8
  Bottom w0.19: 59.367,36.769 59.367,34.393 59.515,34.245 59.533,34.264 J15.72@60.23,34.264
  Bottom w0.2: v1(6.925,32.775) 23.581,32.775 SDCARD.1@26.25,35.444 28.921,35.444 32.984,31.381 36.719,31.381 39.664,34.326 39.664,40.681 40.417,41.433 53.163,41.433 54.214,40.382 54.214,40.121 54.858,39.477 54.873,39.477 57.128,37.222 58.914,37.222 59.367,36.769
  other v1: 59.39,34.316
VSYS: J1.53 J1.64 J15.53 J15.64 TP1.X | length 119
  Top w0.19: v1(35.07,65.236) 35.017,65.183 35.017,47.667 36.615,46.069 37.912,46.069 40.165,43.817 40.165,42.824 v1(42.215,40.774)
  Top w0.2: TP1.X@34.175,67.471 34.175,66.13 v1(35.07,65.236) ; J1.53@57.39,30.664 58.453,30.664 58.632,30.843 v1(58.673,30.843) ; v1(59.349,32.618) 59.395,32.664 J1.64@60.47,32.664 61.906,32.664 61.941,32.629 63.878,32.629 66.598,35.349 66.598,55.961 v1(66.138,56.421)
  Bottom w0.19: v1(42.215,40.774) 42.562,40.427 44.624,38.365 45.147,38.365 53.508,30.004 54.219,30.004 54.562,30.347 54.87,30.347 54.892,30.369 55.411,30.369 55.996,30.954 56.447,30.954 56.737,30.664 J15.53@57.65,30.664 58.45,30.664 58.629,30.843 v1(58.673,30.843) ; v1(59.349,32.618) 59.395,32.664 J15.64@60.23,32.664
  Bottom w0.2: v1(35.07,65.236) 36.655,63.65 49.178,63.65 56.407,56.421 v1(66.138,56.421)
pads on no net: FD1.1 FD2.1 FD3.1 J4.1 J4.3 J4.6 J4.7 J4.8 J4.9 J4.MH1 J4.MH2 J4.MP1 J4.MP2 J7.S1 J7.S2 J15.1 J15.3 J15.5 J15.7 J15.9 J15.11 J15.13 J15.15 J15.17 J15.19 J15.23 J15.25 J15.27 J15.29 J15.M1 J15.M2 J15.M3 J15.M4 J16.M1 J16.M2 J16.M3 J16.M4 JTAG.7 JTAG.11 JTAG.13 JTAG.15 JTAG.17 JTAG.19 S1. S1.2 S2. S2.2 U1.5 U1.6 U1.8

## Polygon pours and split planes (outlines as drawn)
+3V3 on PWR "+3V3_L03_P007" (solid, remove dead copper, pour order 7): 0,72.136 163.957,72.136 163.957,0 0,0
+5V on PWR "PWR-+5V" (solid, remove dead copper, pour order 5): 46.101,42.676 51.439,37.338 56.896,37.338 56.896,41.529 58.039,42.672 63.373,42.672 63.754,42.291 63.754,38.862 62.865,38.862 57.785,33.782 57.785,31.121 61.71,27.166 65.893,22.982 81.266,22.982 81.266,2.046 81.222,2.002 75.572,2.002 75.572,20.334 70.231,20.334 58.43,20.375 50.06,28.745 39.093,28.745 39.093,68.445 39.071,69.382 45.484,69.406 45.484,42.676
GND on Bottom "GND-BOTTOM" (solid, remove dead copper, pour order 0): 0,0 163.957,0 163.957,72.136 0,72.136
GND on GND "GND_L02_P001" (solid, remove dead copper, pour order 1): 0,72.136 163.957,72.136 163.957,0 0,0
GND on Top "GND-TOP" (solid, remove dead copper, pour order 10): 0,0 163.957,0 163.957,72.136 0,72.136

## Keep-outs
Bottom:
  circle w0.254: c161.207,8.4 r2.25
  circle w0.254: c161.207,63.6 r2.25
  circle w0.254: c2.75,63.6 r2.25
  circle w0.254: c2.75,8.4 r2.25
  circle w0.254: c105.855,57.404 r2.25
  circle w0.254: c58.102,14.732 r2.25

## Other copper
Top:
  rectangle net GND: 113.446,24.268 138.38,27.895
  pour cut-out: 17.716,26.758 17.716,23.329 19.748,23.329 19.748,26.758
  pour cut-out: 13.271,26.758 13.271,23.329 15.303,23.329 15.303,26.758

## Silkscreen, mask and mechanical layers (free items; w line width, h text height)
Top Overlay:
  drawing of 710 lines, arcs and shapes, not listed
Bottom Overlay:
  drawing of 61 lines, arcs and shapes, not listed
Top Solder:
  drawing of 24 lines, arcs and shapes, not listed
Top 3D Body:
  lines w0.003: 120.93,61.7 141.25,61.7 141.25,69.32 120.93,69.32 ; 120.93,61.7 120.93,69.32 ; 120.93,61.7 105.69,61.7 105.69,68.05 105.69,69.32 120.93,69.32
Route Tool Path:
  lines w2: -1,5 -1,2 ccw(c2,2) 2,-1 5,-1 ; -1,32.61 -1,34.558 0.7,36.258 0.7,48.586 -1,50.286 -1,52.2 ; -1,67.136 -1,70.136 cw(c2,70.136) 2,73.136 5,73.136 ; 158.957,-1 161.957,-1 ccw(c161.957,2) 164.957,2 164.957,5 ; 158.957,73.136 161.957,73.136 cw(c161.957,70.136) 164.957,70.136 164.957,67.136
Board:
  lines w0.1: 0,70.078 0,50.7 1.7,49 1.7,35.81 0,34.11 0,2.032 ccw(c2.032,2.032) 2.032,0 161.925,0 ccw(c161.925,2.032) 163.957,2.032 163.957,70.104 ccw(c161.925,70.104) 161.925,72.136 2.193,72.136 2.032,72.136 ccw(c2.032,70.104) 0,70.104
Mechanical 60:
  lines w0.1: 4,0 144,0

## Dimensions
102.11,31.064 to 41.785,43.764 on Dimensions
43.69,43.764 to 43.817,41.732 on Dimensions
58.803,31.064 to 43.69,43.764 on Dimensions
43.817,20.396 to 43.817,18.364 on Dimensions
112.988,25.332 to 116.798,23.3 on Dimensions
60.562,40.733 to 58.53,40.733 on Dimensions
58.93,30.939 to 41.785,43.645 on Dimensions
